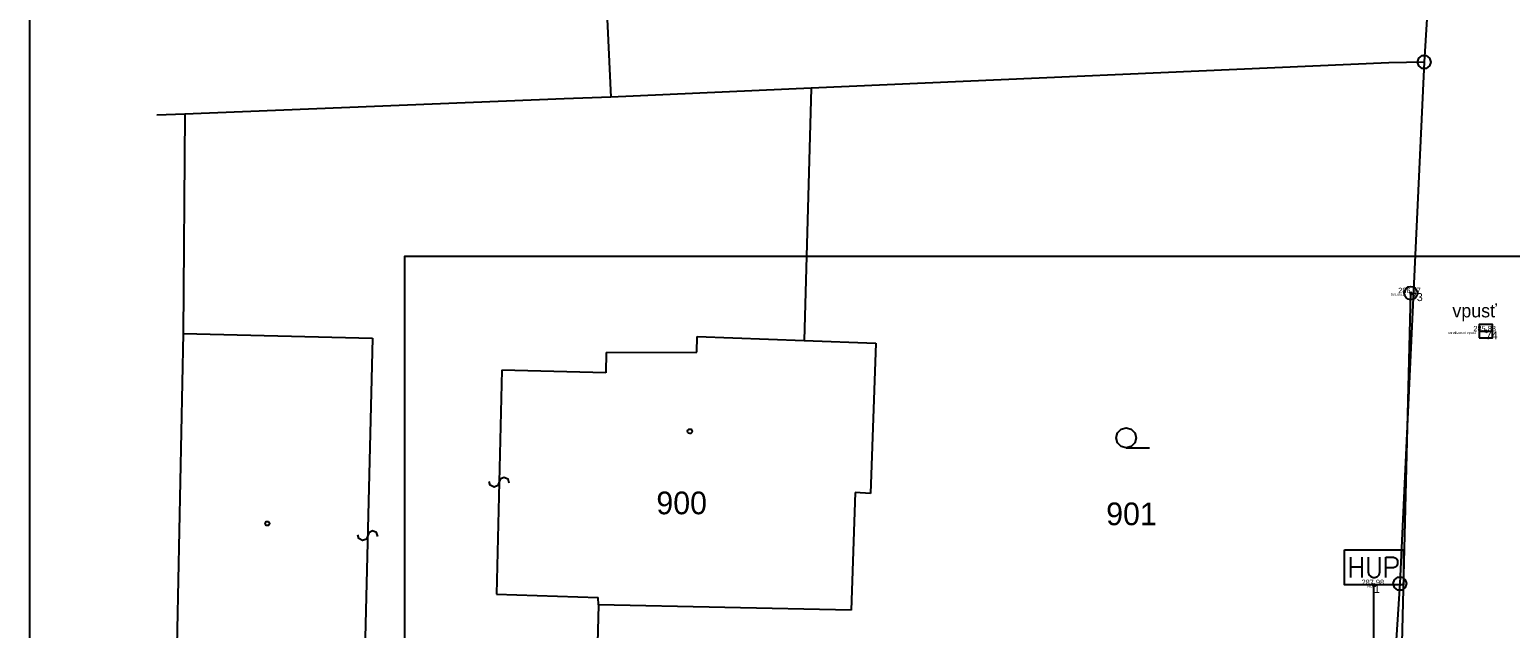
# Model space of a CAD drawing. Extents: x -456675 to -456278, y -1112395 to -1112217.
# Drawn here: x -456383.2 to -456327.7, y -1112289.3 to -1112266.8 of the extents above; entities that cross this region are included whole.
import ezdxf

# ---------------------------------------------------------------- set-up
doc = ezdxf.new("R2010")
doc.units = 0
for name, color, linetype in [('Cislo_bodu', 7, 'Continuous'), ('g_elektrina', 7, 'Continuous'), ('g_kanalizace', 7, 'Continuous'), ('g_ploty', 7, 'Continuous'), ('g_plyn', 7, 'Continuous'), ('Katastralni_mapa', 7, 'Continuous'), ('Kod_bodu', 7, 'Continuous'), ('Ramecek-tisk', 7, 'Continuous'), ('Vyska_bodu', 7, 'Continuous'), ('Znacka_bodu', 7, 'Continuous')]:
    doc.layers.add(name, color=color, linetype=linetype)

msp = doc.modelspace()

# ---------------------------------------------------------------- linework, layer by layer
at = {"layer": 'g_elektrina'}
msp.add_lwpolyline([(-456332.513, -1112319.78), (-456332.123, -1112303.96), (-456331.453, -1112276.72)], dxfattribs=at)
msp.add_circle((-456331.453, -1112276.72), 0.25, dxfattribs=at)
at = {"layer": 'g_kanalizace'}
msp.add_line((-456328.893, -1112278.15), (-456328.393, -1112278.15), dxfattribs=at)
msp.add_lwpolyline([(-456328.893, -1112278.401), (-456328.393, -1112278.401), (-456328.393, -1112277.9), (-456328.893, -1112277.9)], close=True, dxfattribs=at)
at = {"layer": 'g_ploty'}
msp.add_lwpolyline([(-456357.813, -1112299.7), (-456346.273, -1112299.18), (-456339.333, -1112298.84), (-456333.013, -1112298.52), (-456332.843, -1112291.41), (-456332.833, -1112287.66)], dxfattribs=at)
at = {"layer": 'g_plyn'}
for points in [[(-456333.933, -1112286.34), (-456331.733, -1112286.34), (-456331.733, -1112287.66), (-456333.933, -1112287.66), (-456333.933, -1112286.34)], [(-456333.713, -1112286.615), (-456333.713, -1112287.385)], [(-456333.713, -1112286.978), (-456333.271, -1112286.978)], [(-456333.271, -1112287.385), (-456333.271, -1112286.615)], [(-456333.053, -1112286.615), (-456333.053, -1112287.167), (-456333.022, -1112287.275), (-456332.954, -1112287.348), (-456332.861, -1112287.385), (-456332.798, -1112287.385), (-456332.705, -1112287.348), (-456332.642, -1112287.275), (-456332.611, -1112287.167), (-456332.611, -1112286.615)], [(-456332.393, -1112286.615), (-456332.107, -1112286.615), (-456332.015, -1112286.652), (-456331.982, -1112286.688), (-456331.951, -1112286.76), (-456331.951, -1112286.87), (-456331.982, -1112286.943), (-456332.015, -1112286.978), (-456332.107, -1112287.015), (-456332.393, -1112287.015)], [(-456332.393, -1112287.385), (-456332.393, -1112286.615)]]:
    msp.add_lwpolyline(points, dxfattribs=at)
at = {"layer": 'Katastralni_mapa'}
for points in [[(-456362.653, -1112243.25), (-456361.433, -1112269.37)], [(-456329.593, -1112245.9), (-456330.953, -1112268.06)], [(-456332.283, -1112268.09), (-456353.923, -1112269.04)], [(-456330.953, -1112268.06), (-456332.283, -1112268.09)], [(-456330.953, -1112268.06), (-456331.863, -1112287.61)], [(-456330.978, -1112268.06), (-456330.928, -1112268.06)], [(-456353.923, -1112269.04), (-456361.433, -1112269.37)], [(-456353.923, -1112269.04), (-456354.193, -1112278.5)], [(-456363.183, -1112269.44), (-456377.403, -1112270.01)], [(-456361.433, -1112269.37), (-456363.183, -1112269.44)], [(-456377.403, -1112270.01), (-456378.444, -1112270.052)], [(-456377.403, -1112270.01), (-456377.463, -1112278.24)], [(-456377.463, -1112278.24), (-456377.763, -1112293.03)], [(-456377.463, -1112278.24), (-456370.363, -1112278.41)], [(-456370.363, -1112278.41), (-456370.723, -1112293.22)], [(-456358.213, -1112278.94), (-456358.193, -1112278.35)], [(-456358.193, -1112278.35), (-456354.193, -1112278.5)], [(-456354.193, -1112278.5), (-456351.503, -1112278.6)], [(-456351.503, -1112278.6), (-456351.703, -1112284.23)], [(-456361.603, -1112278.95), (-456361.623, -1112279.71)], [(-456361.603, -1112278.95), (-456358.213, -1112278.94)], [(-456365.513, -1112279.61), (-456365.713, -1112288.01)], [(-456361.623, -1112279.71), (-456365.513, -1112279.61)], [(-456342.12, -1112282.523), (-456342.31, -1112282.473), (-456342.445, -1112282.333), (-456342.495, -1112282.148), (-456342.445, -1112281.963), (-456342.31, -1112281.823), (-456342.12, -1112281.773), (-456341.93, -1112281.823), (-456341.795, -1112281.963), (-456341.745, -1112282.148), (-456341.795, -1112282.333), (-456341.93, -1112282.473), (-456342.12, -1112282.523), (-456341.245, -1112282.523)], [(-456365.239, -1112283.844), (-456365.285, -1112283.693), (-456365.439, -1112283.629), (-456365.576, -1112283.696), (-456365.666, -1112283.934), (-456365.808, -1112283.99), (-456365.951, -1112283.917), (-456365.988, -1112283.776)], [(-456352.283, -1112284.2), (-456352.423, -1112288.61)], [(-456351.703, -1112284.23), (-456352.283, -1112284.2)], [(-456370.169, -1112285.849), (-456370.215, -1112285.698), (-456370.369, -1112285.634), (-456370.506, -1112285.701), (-456370.596, -1112285.939), (-456370.738, -1112285.995), (-456370.881, -1112285.922), (-456370.918, -1112285.781)], [(-456331.863, -1112287.61), (-456332.573, -1112298.58)], [(-456331.888, -1112287.61), (-456331.838, -1112287.61)], [(-456365.713, -1112288.01), (-456361.903, -1112288.13)], [(-456361.893, -1112288.41), (-456361.903, -1112288.13)], [(-456361.893, -1112288.41), (-456362.193, -1112299.87)], [(-456352.423, -1112288.61), (-456361.893, -1112288.41)]]:
    msp.add_lwpolyline(points, dxfattribs=at)
for points in [[(-456330.878, -1112267.82), (-456330.753, -1112267.915), (-456330.703, -1112268.06), (-456330.753, -1112268.205), (-456330.878, -1112268.3), (-456331.028, -1112268.3), (-456331.153, -1112268.205), (-456331.203, -1112268.06), (-456331.153, -1112267.915), (-456331.028, -1112267.82)], [(-456358.473, -1112281.815), (-456358.423, -1112281.825), (-456358.398, -1112281.87), (-456358.388, -1112281.9), (-456358.398, -1112281.945), (-456358.438, -1112281.98), (-456358.473, -1112281.985), (-456358.518, -1112281.97), (-456358.548, -1112281.94), (-456358.558, -1112281.9), (-456358.548, -1112281.855), (-456358.508, -1112281.82)], [(-456374.258, -1112285.275), (-456374.213, -1112285.35), (-456374.258, -1112285.425), (-456374.348, -1112285.425), (-456374.393, -1112285.35), (-456374.348, -1112285.275)], [(-456331.788, -1112287.37), (-456331.663, -1112287.465), (-456331.613, -1112287.61), (-456331.663, -1112287.755), (-456331.788, -1112287.85), (-456331.938, -1112287.85), (-456332.063, -1112287.755), (-456332.113, -1112287.61), (-456332.063, -1112287.465), (-456331.938, -1112287.37)]]:
    msp.add_lwpolyline(points, close=True, dxfattribs=at)
at = {"layer": 'Ramecek-tisk'}
for points in [[(-456383.215, -1112373.688), (-456278.215, -1112373.688), (-456278.215, -1112225.188), (-456383.215, -1112225.188)], [(-456294.921, -1112327.842), (-456294.921, -1112275.342), (-456369.171, -1112275.342), (-456369.171, -1112327.842)]]:
    msp.add_lwpolyline(points, close=True, dxfattribs=at)
at = {"layer": 'Znacka_bodu'}
for p, q in [((-456331.453, -1112276.72), (-456331.503, -1112276.67)), ((-456331.453, -1112276.72), (-456331.503, -1112276.77)), ((-456331.453, -1112276.72), (-456331.403, -1112276.67)), ((-456331.453, -1112276.72), (-456331.403, -1112276.77)), ((-456328.643, -1112278.15), (-456328.693, -1112278.1)), ((-456328.643, -1112278.15), (-456328.693, -1112278.2)), ((-456328.643, -1112278.15), (-456328.593, -1112278.1)), ((-456328.643, -1112278.15), (-456328.593, -1112278.2)), ((-456332.833, -1112287.66), (-456332.883, -1112287.61)), ((-456332.833, -1112287.66), (-456332.783, -1112287.61)), ((-456332.833, -1112287.66), (-456332.883, -1112287.71)), ((-456332.833, -1112287.66), (-456332.783, -1112287.71))]:
    msp.add_line(p, q, dxfattribs=at)

# ---------------------------------------------------------------- texts
at = {"layer": 'Cislo_bodu'}
for s, p in [('73', (-456331.453, -1112277.02)), ('74', (-456328.643, -1112278.45)), ('1', (-456332.833, -1112287.96))]:
    msp.add_text(s, height=0.3, dxfattribs=at).set_placement(p)
at = {"layer": 'g_kanalizace'}
msp.add_text('vpusť', height=0.5, dxfattribs=at).set_placement((-456329.894, -1112277.63))
at = {"layer": 'Katastralni_mapa'}
for s, p in [('900', (-456359.727, -1112285.01)), ('901', (-456342.87, -1112285.42))]:
    msp.add_text(s, height=0.85, dxfattribs=at).set_placement(p)
at = {"layer": 'Kod_bodu'}
for s, p in [('bet.sloup', (-456332.193, -1112276.82)), ('kanalizacni vpust', (-456330.075, -1112278.25)), ('HUP', (-456333.081, -1112287.76))]:
    msp.add_text(s, height=0.1, dxfattribs=at).set_placement(p)
at = {"layer": 'Vyska_bodu'}
for s, p in [('286.97', (-456331.924, -1112276.72)), ('285.88', (-456329.108, -1112278.15)), ('287.98', (-456333.299, -1112287.66))]:
    msp.add_text(s, height=0.2, dxfattribs=at).set_placement(p)

doc.saveas('drawing.dxf')
